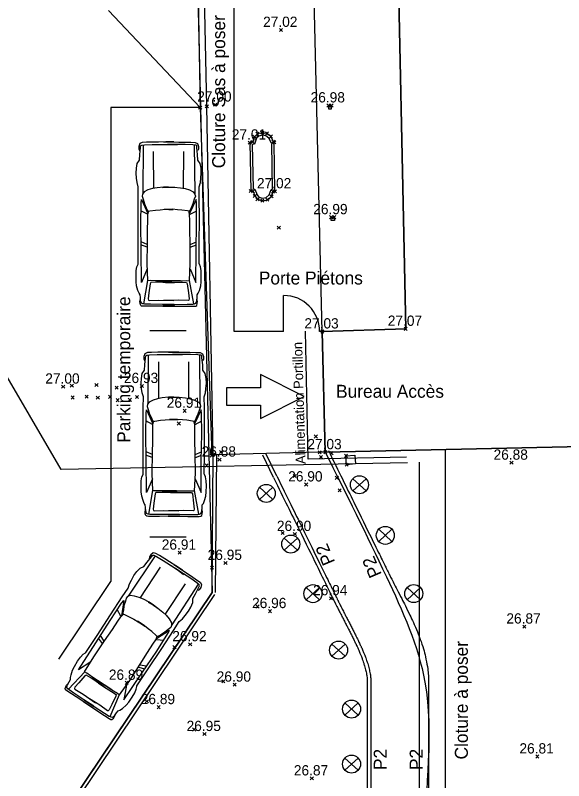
# Model space of a CAD drawing. Extents: x 37864 to 38032, y 453991 to 454052.
# Drawn here: x 37894.08 to 37909.31, y 454007.62 to 454028.87 of the extents above; entities that cross this region are included whole.
import ezdxf

# ---------------------------------------------------------------- set-up
doc = ezdxf.new("R2010")
doc.units = 0
for name, color, linetype in [('DH_CALCUL SURFACE-TEXTE', 7, 'Continuous'), ('GO MUR EXTERIEUR', 7, 'Continuous'), ('GO_MUR_INTERIEUR', 7, 'Continuous'), ('GO_POTEAU', 7, 'Continuous'), ('PS_Bolt', 7, 'Continuous'), ('PS_Dim', 7, 'Continuous'), ('PS_Hatch', 7, 'Continuous'), ('PS_Hidden', 7, 'Continuous'), ('PS_Mid', 7, 'Continuous'), ('PS_Object', 7, 'Continuous'), ('PS_Shape', 7, 'Continuous'), ('PS_Solid', 7, 'Continuous'), ('PS_Text', 7, 'Continuous'), ('PS_Weld', 7, 'Continuous'), ('SO_SANITAIRE DETAILLE', 7, 'Continuous')]:
    doc.layers.add(name, color=color, linetype=linetype)

# ---------------------------------------------------------------- blocks, each defined once
blk = doc.blocks.new('POTO_REC')
at = {"layer": 'PS_Weld'}
for p, q in [((0, 1), (1, 1)), ((0, 0), (0, 1)), ((1, 1), (1, 0)), ((1, 0), (0, 0))]:
    blk.add_line(p, q, dxfattribs=at)
blk = doc.blocks.new('POINT_DISPLAY')
for p, q in [((-0.04375, -0.04375), (0.04375, 0.04375)), ((-0.04375, 0.04375), (0.04375, -0.04375))]:
    blk.add_line(p, q)
blk = doc.blocks.new('POINTCOT')
blk.add_blockref('POINT_DISPLAY', (0, 0))
blk = doc.blocks.new('2AUTOT')
at = {"layer": 'PS_Object'}
for points in [[(-2.2368, -0.1259), (-2.2386, 0.2015), (-2.2354, 0.5377), (-2.2324, 0.697), (-2.2268, 0.7426), (-2.2084, 0.7838), (-2.144, 0.8083), (-2.0432, 0.8164), (-1.9712, 0.8202), (-1.9275, 0.8508), (-1.8518, 0.8827), (-1.7249, 0.9185), (-1.608, 0.9323), (-1.4401, 0.9339), (-1.298, 0.9313), (-1.1945, 0.9113), (-1.1215, 0.8812), (-1.1104, 0.8767), (-0.5447, 0.878), (0.1409, 0.8813), (0.7386, 0.8794), (1.0309, 0.8727), (1.1466, 0.9086), (1.2652, 0.9239), (1.4092, 0.9345), (1.5433, 0.9275), (1.677, 0.9028), (1.7685, 0.8402), (1.9202, 0.833), (2.1132, 0.8123), (2.1691, 0.8089), (2.1877, 0.7793), (2.1974, 0.6996), (2.2046, 0.4901), (2.2064, 0.2453), (2.2048, -0.0084), (2.1947, -0.2029)], [(2.2747, -0.1136), (2.2724, 0.1046), (2.27, 0.3126), (2.2713, 0.4704), (2.2666, 0.6444), (2.2593, 0.761), (2.2286, 0.8291), (2.1508, 0.8577), (2.0757, 0.8569), (2.0322, 0.8366)], [(-2.2848, -0.1314), (-2.2888, 0.4217), (-2.2909, 0.7314), (-2.2836, 0.7814), (-2.2655, 0.8064), (-2.2141, 0.8192), (-2.1613, 0.8262), (-2.1183, 0.817), (-2.0976, 0.8109)], [(-2.2271, 0.7235), (-1.5742, 0.6061)], [(-1.2494, 0.6227), (-1.6267, 0.7865), (-0.7381, 0.7926), (0.002, 0.8043), (0.5788, 0.7967), (0.6713, 0.7886), (0.2844, 0.6088)], [(-0.65, 0.6296), (-0.5861, 0.8002)], [(-0.5719, 0.6231), (-0.4967, 0.7965)], [(0.2639, 0.6208), (0.3616, 0.8058)], [(1.007, -0.1403), (1.0182, 0.0307), (1.0193, 0.1767), (1.0035, 0.3523), (0.9788, 0.4823), (0.9395, 0.605), (0.8856, 0.7131), (0.8242, 0.7593), (0.7669, 0.7701), (0.68, 0.7398), (0.5514, 0.701), (0.445, 0.6503), (0.3774, 0.6228), (0.3483, 0.6068), (0.3601, 0.5536), (0.3827, 0.3957), (0.3915, 0.2688), (0.4032, 0.1301), (0.4012, 0.0239), (0.4006, -0.0941)], [(2.1886, 0.7409), (0.8432, 0.7503)], [(-1.6299, -0.0629), (-1.6283, 0.1907), (-1.6233, 0.3735), (-1.6284, 0.5254), (-1.6632, 0.5449), (-1.9214, 0.5809), (-2.084, 0.5999), (-2.1242, 0.5899), (-2.1341, 0.5723), (-2.1215, 0.3067), (-2.1311, -0.1149)], [(-1.5848, -0.2978), (-1.5832, -0.0427), (-1.5806, 0.1815), (-1.5811, 0.4086), (-1.5755, 0.5339), (-1.5821, 0.6091), (-1.0895, 0.6288), (-0.5543, 0.6215), (-0.1709, 0.614), (0.1055, 0.6117), (0.2493, 0.6106), (0.3289, 0.5937), (0.3607, 0.5846)], [(0.9812, 0.4439), (2.0072, 0.4474)], [(-2.2368, 0.1834), (-2.2386, -0.144), (-2.2354, -0.4802), (-2.2324, -0.6394), (-2.2268, -0.6851), (-2.2084, -0.7263), (-2.144, -0.7508), (-2.0432, -0.7588), (-1.9712, -0.7627), (-1.9275, -0.7933), (-1.8518, -0.8251), (-1.7249, -0.861), (-1.608, -0.8748), (-1.4401, -0.8764), (-1.298, -0.8738), (-1.1945, -0.8538), (-1.1215, -0.8237), (-1.1104, -0.8192), (-0.5447, -0.8205), (0.1409, -0.8238), (0.7386, -0.8219), (1.0309, -0.8151), (1.1466, -0.8511), (1.2652, -0.8663), (1.4092, -0.877), (1.5433, -0.87), (1.677, -0.8453), (1.7685, -0.7827), (1.9202, -0.7755), (2.1132, -0.7548), (2.1691, -0.7514), (2.1877, -0.7218), (2.1974, -0.642), (2.2046, -0.4326), (2.2064, -0.1878), (2.2048, 0.0659), (2.1947, 0.2605)], [(-1.5848, 0.3553), (-1.5832, 0.1002), (-1.5806, -0.1239), (-1.5811, -0.351), (-1.5755, -0.4764), (-1.5821, -0.5516), (-1.0895, -0.5712), (-0.5543, -0.564), (-0.1709, -0.5565), (0.1055, -0.5542), (0.2493, -0.5531), (0.3289, -0.5362), (0.3607, -0.5271)], [(-2.2848, 0.1889), (-2.2888, -0.3641), (-2.2909, -0.6738), (-2.2836, -0.7239), (-2.2655, -0.7488), (-2.2141, -0.7617), (-2.1613, -0.7686), (-2.1183, -0.7595), (-2.0976, -0.7534)], [(-1.6299, 0.1205), (-1.6283, -0.1332), (-1.6233, -0.316), (-1.6284, -0.4679), (-1.6632, -0.4874), (-1.9214, -0.5234), (-2.084, -0.5424), (-2.1242, -0.5324), (-2.1341, -0.5148), (-2.1215, -0.2492), (-2.1311, 0.1725)], [(1.007, 0.1978), (1.0182, 0.0268), (1.0193, -0.1192), (1.0035, -0.2948), (0.9788, -0.4248), (0.9395, -0.5475), (0.8856, -0.6556), (0.8242, -0.7018), (0.7669, -0.7126), (0.68, -0.6823), (0.5514, -0.6435), (0.445, -0.5928), (0.3774, -0.5653), (0.3483, -0.5493), (0.3601, -0.4961), (0.3827, -0.3382), (0.3915, -0.2113), (0.4032, -0.0725), (0.4012, 0.0336), (0.4006, 0.1516)], [(2.2747, 0.1711), (2.2724, -0.0471), (2.27, -0.2551), (2.2713, -0.4129), (2.2666, -0.5869), (2.2593, -0.7035), (2.2286, -0.7716), (2.1508, -0.8002), (2.0757, -0.7993), (2.0322, -0.779)], [(0.9812, -0.3864), (2.0072, -0.3899)], [(-2.2271, -0.666), (-1.5742, -0.5486)], [(-1.2494, -0.5652), (-1.6267, -0.7289), (-0.7381, -0.735), (0.002, -0.7468), (0.5788, -0.7392), (0.6713, -0.731), (0.2844, -0.5513)], [(-0.65, -0.5721), (-0.5861, -0.7427)], [(-0.5719, -0.5656), (-0.4967, -0.739)], [(0.2639, -0.5633), (0.3616, -0.7483)], [(2.1886, -0.6834), (0.8432, -0.6928)]]:
    blk.add_lwpolyline(points, dxfattribs=at)
blk = doc.blocks.new('AUTD')
at = {"layer": 'PS_Object'}
blk.add_blockref('2AUTOT', (-2.1886, 0.6834), dxfattribs=at)
blk = doc.blocks.new('BORNANTI')
for p, q in [((-0.369, -0.338), (0.369, 0.338)), ((-0.369, 0.338), (0.369, -0.338))]:
    blk.add_line(p, q)
blk.add_circle((0, 0), 0.5)

msp = doc.modelspace()

# ---------------------------------------------------------------- linework, layer by layer
at = {"layer": 'GO MUR EXTERIEUR'}
msp.add_lwpolyline([(37904.652, 454032.841), (37904.92, 454020.167), (37902.603, 454020.093), (37902.686, 454016.74), (37922.017, 454017.171), (37921.708, 454033.195)], close=True, dxfattribs=at)
at = {"layer": 'GO_MUR_INTERIEUR'}
msp.add_lwpolyline([(37899.06, 454034.436), (37899.21, 454026.312), (37899.534, 454016.645)], dxfattribs=at)
at = {"layer": 'PS_Bolt'}
for points in [[(37901.27, 454025.348), (37901.249, 454025.367), (37901.177, 454025.51), (37901.065, 454025.594), (37900.941, 454025.614), (37900.801, 454025.583), (37900.719, 454025.503), (37900.664, 454025.358), (37900.588, 454025.34), (37900.618, 454023.996), (37900.679, 454023.987), (37900.729, 454023.857), (37900.803, 454023.766), (37900.94, 454023.726), (37901.078, 454023.753), (37901.192, 454023.847), (37901.233, 454023.975), (37901.286, 454023.986), (37901.27, 454025.348)], [(37901.2, 454025.317), (37901.192, 454025.324), (37901.122, 454025.464), (37901.037, 454025.528), (37900.943, 454025.543), (37900.836, 454025.519), (37900.779, 454025.463), (37900.716, 454025.298), (37900.659, 454025.285), (37900.687, 454024.057), (37900.73, 454024.05), (37900.79, 454023.892), (37900.843, 454023.827), (37900.943, 454023.798), (37901.048, 454023.818), (37901.132, 454023.888), (37901.179, 454024.036), (37901.216, 454024.043), (37901.2, 454025.317)]]:
    msp.add_lwpolyline(points, dxfattribs=at)
at = {"layer": 'PS_Dim'}
for p, q in [((37900.154, 454020.093), (37900.154, 454030.534)), ((37901.53, 454020.093), (37901.53, 454021.093)), ((37901.53, 454020.093), (37900.154, 454020.093)), ((37902.676, 454020.093), (37902.53, 454020.093)), ((37906.023, 454001.592), (37906.023, 454016.814))]:
    msp.add_line(p, q, dxfattribs=at)
msp.add_arc((37901.53, 454020.093), 1, 360, 90, dxfattribs=at)
at = {"layer": 'PS_Hatch'}
msp.add_lwpolyline([(37902.603, 454020.093), (37902.29, 454032.792), (37904.652, 454032.841), (37904.92, 454020.167), (37902.603, 454020.093)], dxfattribs=at)
at = {"layer": 'PS_Hidden'}
for p, q in [((37896.73, 454026.312), (37896.73, 454013.149)), ((37899.21, 454026.312), (37896.73, 454026.312)), ((37898.82, 454020.114), (37897.814, 454020.114)), ((37901.34, 454016.079), (37901.039, 454016.705)), ((37901.249, 454016.035), (37900.949, 454016.662)), ((37898.82, 454014.385), (37897.814, 454014.385))]:
    msp.add_line(p, q, dxfattribs=at)
msp.add_lwpolyline([(37902.1, 454018.289), (37900.885, 454018.896), (37900.885, 454018.531), (37899.943, 454018.531), (37899.943, 454018.047), (37900.885, 454018.047), (37900.885, 454017.681)], close=True, dxfattribs=at)
msp.add_spline([(37902.686, 454016.74), (37904.384, 454013.284), (37905.453, 454010.356), (37905.453, 454005.953), (37905.453, 454003.832), (37904.955, 454001.594)], degree=3, dxfattribs=at)
for points in [[(37902.776, 454016.784), (37903.066, 454016.194), (37903.501, 454015.308), (37904.008, 454014.275), (37904.262, 454013.759), (37904.389, 454013.501), (37904.446, 454013.385), (37904.466, 454013.344), (37904.471, 454013.335), (37904.473, 454013.33), (37904.48, 454013.316), (37904.493, 454013.289), (37904.507, 454013.261), (37904.589, 454013.096), (37904.666, 454012.948), (37904.821, 454012.649), (37904.899, 454012.498), (37905.049, 454012.194), (37905.122, 454012.04), (37905.256, 454011.728), (37905.318, 454011.57), (37905.423, 454011.25), (37905.466, 454011.087), (37905.529, 454010.758), (37905.549, 454010.59), (37905.553, 454010.399), (37905.553, 454010.378), (37905.553, 454010.356), (37905.553, 454010.356), (37905.553, 454010.355), (37905.553, 454010.354), (37905.553, 454010.352), (37905.553, 454010.347), (37905.553, 454010.338), (37905.553, 454010.32), (37905.553, 454010.264), (37905.553, 454010.13), (37905.553, 454009.843), (37905.553, 454008.938), (37905.553, 454007.787), (37905.553, 454006.636), (37905.553, 454006.138), (37905.553, 454005.966), (37905.553, 454005.958), (37905.553, 454005.953), (37905.553, 454005.95), (37905.553, 454005.938), (37905.553, 454005.907), (37905.554, 454005.876), (37905.554, 454005.815), (37905.555, 454005.774), (37905.557, 454005.652), (37905.559, 454005.57), (37905.567, 454005.323), (37905.574, 454005.158), (37905.584, 454004.827), (37905.588, 454004.661), (37905.587, 454004.328), (37905.582, 454004.162), (37905.566, 454003.955), (37905.562, 454003.913), (37905.556, 454003.851), (37905.554, 454003.83), (37905.549, 454003.789), (37905.547, 454003.768), (37905.534, 454003.665), (37905.522, 454003.583), (37905.481, 454003.337), (37905.448, 454003.174), (37905.374, 454002.85), (37905.334, 454002.689), (37905.251, 454002.369), (37905.209, 454002.209), (37905.128, 454001.89), (37905.088, 454001.731), (37905.053, 454001.572)], [(37901.34, 454016.079), (37901.63, 454015.488), (37902.065, 454014.603), (37902.572, 454013.57), (37902.826, 454013.053), (37902.953, 454012.795), (37903.01, 454012.68), (37903.031, 454012.636), (37903.035, 454012.628), (37903.037, 454012.624), (37903.038, 454012.623), (37903.038, 454012.622), (37903.038, 454012.622), (37903.039, 454012.621), (37903.044, 454012.61), (37903.049, 454012.599), (37903.065, 454012.568), (37903.075, 454012.548), (37903.125, 454012.447), (37903.166, 454012.368), (37903.245, 454012.213), (37903.285, 454012.137), (37903.361, 454011.989), (37903.399, 454011.916), (37903.471, 454011.774), (37903.506, 454011.705), (37903.573, 454011.57), (37903.605, 454011.504), (37903.665, 454011.375), (37903.693, 454011.313), (37903.745, 454011.191), (37903.769, 454011.132), (37903.813, 454011.019), (37903.832, 454010.964), (37903.867, 454010.859), (37903.882, 454010.808), (37903.907, 454010.712), (37903.918, 454010.666), (37903.935, 454010.578), (37903.941, 454010.537), (37903.95, 454010.457), (37903.952, 454010.42), (37903.953, 454010.374), (37903.953, 454010.365), (37903.953, 454010.356), (37903.953, 454010.356), (37903.953, 454010.356), (37903.953, 454010.356), (37903.953, 454010.355), (37903.953, 454010.354), (37903.953, 454010.352), (37903.953, 454010.347), (37903.953, 454010.338), (37903.953, 454010.32), (37903.953, 454010.264), (37903.953, 454010.13), (37903.953, 454009.843), (37903.953, 454008.938), (37903.953, 454007.787), (37903.953, 454006.636), (37903.953, 454006.138), (37903.953, 454005.966), (37903.953, 454005.957), (37903.953, 454005.954), (37903.953, 454005.953), (37903.953, 454005.953), (37903.953, 454005.953), (37903.953, 454005.952), (37903.953, 454005.95), (37903.953, 454005.936), (37903.953, 454005.923), (37903.953, 454005.888), (37903.954, 454005.864), (37903.954, 454005.795), (37903.955, 454005.749), (37903.958, 454005.612), (37903.96, 454005.523), (37903.966, 454005.35), (37903.969, 454005.265), (37903.975, 454005.1), (37903.977, 454005.02), (37903.982, 454004.864), (37903.984, 454004.788), (37903.987, 454004.641), (37903.988, 454004.57), (37903.987, 454004.433), (37903.986, 454004.366), (37903.981, 454004.238), (37903.978, 454004.176), (37903.971, 454004.088), (37903.969, 454004.059), (37903.965, 454004.023), (37903.964, 454004.016), (37903.963, 454004.005), (37903.963, 454004.001), (37903.962, 454003.997), (37903.962, 454003.995), (37903.962, 454003.995), (37903.962, 454003.994), (37903.962, 454003.992), (37903.96, 454003.975), (37903.958, 454003.959), (37903.949, 454003.885), (37903.94, 454003.825), (37903.919, 454003.7), (37903.908, 454003.636), (37903.881, 454003.504), (37903.867, 454003.436), (37903.835, 454003.297), (37903.818, 454003.226), (37903.782, 454003.079), (37903.763, 454003.005), (37903.723, 454002.851), (37903.703, 454002.773), (37903.661, 454002.612), (37903.64, 454002.53), (37903.597, 454002.362), (37903.575, 454002.276), (37903.533, 454002.101), (37903.512, 454002.011), (37903.491, 454001.92)], [(37901.25, 454016.035), (37901.54, 454015.444), (37901.975, 454014.559), (37902.483, 454013.526), (37902.736, 454013.009), (37902.863, 454012.751), (37902.918, 454012.64), (37902.938, 454012.599), (37902.941, 454012.592), (37902.945, 454012.585), (37902.946, 454012.582), (37902.947, 454012.58), (37902.948, 454012.579), (37902.948, 454012.579), (37902.948, 454012.578), (37902.948, 454012.578), (37902.949, 454012.577), (37902.949, 454012.576), (37902.955, 454012.565), (37902.96, 454012.555), (37902.975, 454012.524), (37902.985, 454012.503), (37903.036, 454012.402), (37903.077, 454012.322), (37903.156, 454012.167), (37903.196, 454012.091), (37903.272, 454011.943), (37903.31, 454011.87), (37903.382, 454011.729), (37903.417, 454011.66), (37903.483, 454011.526), (37903.515, 454011.461), (37903.574, 454011.334), (37903.602, 454011.272), (37903.653, 454011.153), (37903.676, 454011.095), (37903.719, 454010.984), (37903.738, 454010.931), (37903.771, 454010.829), (37903.786, 454010.781), (37903.81, 454010.688), (37903.82, 454010.645), (37903.836, 454010.562), (37903.842, 454010.523), (37903.85, 454010.449), (37903.852, 454010.414), (37903.853, 454010.377), (37903.853, 454010.373), (37903.853, 454010.367), (37903.853, 454010.364), (37903.853, 454010.36), (37903.853, 454010.358), (37903.853, 454010.357), (37903.853, 454010.357), (37903.853, 454010.357), (37903.853, 454010.356), (37903.853, 454010.356), (37903.853, 454010.356), (37903.853, 454010.356), (37903.853, 454010.356), (37903.853, 454010.355), (37903.853, 454010.355), (37903.853, 454010.354), (37903.853, 454010.352), (37903.853, 454010.347), (37903.853, 454010.338), (37903.853, 454010.32), (37903.853, 454010.264), (37903.853, 454010.13), (37903.853, 454009.843), (37903.853, 454008.938), (37903.853, 454007.787), (37903.853, 454006.636), (37903.853, 454006.143), (37903.853, 454005.973), (37903.853, 454005.966), (37903.853, 454005.958), (37903.853, 454005.955), (37903.853, 454005.954), (37903.853, 454005.953), (37903.853, 454005.953), (37903.853, 454005.952), (37903.853, 454005.95), (37903.853, 454005.948), (37903.853, 454005.935), (37903.853, 454005.923), (37903.853, 454005.887), (37903.854, 454005.864), (37903.854, 454005.793), (37903.855, 454005.747), (37903.858, 454005.61), (37903.86, 454005.52), (37903.866, 454005.346), (37903.869, 454005.261), (37903.875, 454005.097), (37903.878, 454005.017), (37903.882, 454004.861), (37903.884, 454004.786), (37903.887, 454004.64), (37903.888, 454004.57), (37903.887, 454004.434), (37903.886, 454004.368), (37903.881, 454004.243), (37903.878, 454004.182), (37903.872, 454004.096), (37903.869, 454004.068), (37903.866, 454004.033), (37903.865, 454004.026), (37903.864, 454004.016), (37903.864, 454004.013), (37903.863, 454004.008), (37903.863, 454004.008), (37903.863, 454004.006), (37903.863, 454004.006), (37903.863, 454004.005), (37903.862, 454004.003), (37903.862, 454004.001), (37903.86, 454003.985), (37903.859, 454003.971), (37903.85, 454003.899), (37903.841, 454003.84), (37903.821, 454003.718), (37903.809, 454003.654), (37903.783, 454003.525), (37903.769, 454003.458), (37903.738, 454003.32), (37903.721, 454003.249), (37903.685, 454003.104), (37903.666, 454003.029), (37903.627, 454002.876), (37903.606, 454002.798), (37903.564, 454002.637), (37903.543, 454002.555), (37903.5, 454002.387), (37903.478, 454002.3), (37903.435, 454002.124), (37903.414, 454002.034), (37903.394, 454001.941)]]:
    msp.add_open_spline(points, degree=3, dxfattribs=at)
at = {"layer": 'PS_Mid'}
msp.add_lwpolyline([(37902.686, 454016.74), (37902.53, 454016.739), (37899.575, 454016.672), (37899.397, 454026.348), (37899.231, 454034.242), (37905.827, 454034.425), (37913.049, 454034.558), (37921.676, 454034.732), (37921.802, 454033.217), (37921.708, 454033.195)], dxfattribs=at)
at = {"layer": 'PS_Object'}
for p, q in [((37895.353, 454016.257), (37888.689, 454027.599)), ((37905.292, 454016.464), (37905.292, 454001.738)), ((37904.969, 454016.447), (37895.353, 454016.257))]:
    msp.add_line(p, q, dxfattribs=at)
for points in [[(37889.343, 454030.528), (37899.117, 454030.549), (37899.54, 454012.849), (37895.242, 454006.442), (37895.242, 454005.264), (37889.943, 454005.178)], [(37904.94, 454016.607), (37902.211, 454016.551), (37902.139, 454020.1)]]:
    msp.add_lwpolyline(points, dxfattribs=at)
at = {"layer": 'PS_Shape'}
msp.add_line((37895.285, 454010.994), (37896.73, 454013.149), dxfattribs=at)
at = {"layer": 'PS_Solid'}
msp.add_lwpolyline([(37921.708, 454033.195), (37922.017, 454017.171), (37902.686, 454016.74), (37902.603, 454020.093), (37904.92, 454020.167), (37904.652, 454032.841), (37921.708, 454033.195)], dxfattribs=at)
at = {"layer": 'PS_Text'}
for points in [[(37902.774, 454026.281), (37902.859, 454026.279), (37902.861, 454026.369), (37902.776, 454026.371)], [(37902.85, 454023.268), (37902.936, 454023.27), (37902.938, 454023.18), (37902.852, 454023.178)]]:
    msp.add_lwpolyline(points, close=True, dxfattribs=at)
at = {"layer": 'SO_SANITAIRE DETAILLE'}
for p, q in [((37896.668, 454029.009), (37899.21, 454026.312)), ((37899.54, 454012.849), (37899.575, 454016.672)), ((37899.64, 454012.848), (37899.675, 454016.671)), ((37895.242, 454006.442), (37899.54, 454012.849)), ((37895.325, 454006.386), (37899.623, 454012.793))]:
    msp.add_line(p, q, dxfattribs=at)

# ---------------------------------------------------------------- block references
at = {"layer": 'DH_CALCUL SURFACE-TEXTE', "rotation": 2.2526485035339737e-05}
for p in [(37901.457, 454028.469), (37899.21, 454026.312), (37899.397, 454026.348), (37899.628, 454026.395), (37902.776, 454026.371), (37902.861, 454026.369), (37900.801, 454025.583), (37900.941, 454025.614), (37901.065, 454025.594), (37900.664, 454025.358), (37900.719, 454025.503), (37901.177, 454025.51), (37901.249, 454025.367), (37900.588, 454025.34), (37901.27, 454025.348), (37900.618, 454023.996), (37900.679, 454023.987), (37901.233, 454023.975), (37901.286, 454023.986), (37900.729, 454023.857), (37900.803, 454023.766), (37900.94, 454023.726), (37901.078, 454023.753), (37901.192, 454023.847), (37902.85, 454023.268), (37902.936, 454023.27), (37901.397, 454022.975), (37902.603, 454020.093), (37904.92, 454020.167), (37904.92, 454020.167), (37895.407, 454018.562), (37895.647, 454018.588), (37896.33, 454018.605), (37897.59, 454018.578), (37896.893, 454018.535), (37895.67, 454018.26), (37896.059, 454018.283), (37896.369, 454018.256), (37896.707, 454018.28), (37896.92, 454018.188), (37897.259, 454018.196), (37897.457, 454018.275), (37898.781, 454017.891), (37898.617, 454017.537), (37902.422, 454017.176), (37899.534, 454016.645), (37899.575, 454016.672), (37899.79, 454016.749), (37902.53, 454016.739), (37902.686, 454016.74), (37902.864, 454016.715), (37903.261, 454016.638), (37899.75, 454016.536), (37902.566, 454016.609), (37907.858, 454016.448), (37899.392, 454016.373), (37903.28, 454016.394), (37901.836, 454016.078), (37903.007, 454016.027), (37902.154, 454015.845), (37903.088, 454015.684), (37901.502, 454014.496), (37901.84, 454014.469), (37898.642, 454013.949), (37899.916, 454013.665), (37899.538, 454013.535), (37902.846, 454012.684), (37900.804, 454012.454), (37901.15, 454012.328), (37908.214, 454011.898), (37898.498, 454011.325), (37898.934, 454011.406), (37897.172, 454010.335), (37899.853, 454010.379), (37900.168, 454010.284), (37897.728, 454009.824), (37898.059, 454009.66), (37899.044, 454009.041), (37899.331, 454008.913), (37908.577, 454008.289), (37902.311, 454007.681)]:
    msp.add_blockref('POINTCOT', p, dxfattribs=at)
at = {"layer": 'PS_Bolt'}
for name, p, xscale, yscale, rotation in [('POTO_REC', (37903.28, 454016.394), 0.24999999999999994, 0.24999999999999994, 4.495003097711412), ('BORNANTI', (37903.635, 454015.836), 0.5000000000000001, 0.5, 2.2526485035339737e-05), ('BORNANTI', (37901.048, 454015.597), 0.5000000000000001, 0.5, 2.2526485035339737e-05), ('BORNANTI', (37904.354, 454014.432), 0.5000000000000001, 0.5, 2.2526485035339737e-05), ('BORNANTI', (37901.726, 454014.189), 0.5000000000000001, 0.5, 2.2526485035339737e-05), ('BORNANTI', (37905.145, 454012.814), 0.5000000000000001, 0.5, 2.2526485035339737e-05), ('BORNANTI', (37902.342, 454012.812), 0.5000000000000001, 0.5, 2.2526485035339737e-05), ('BORNANTI', (37903.056, 454011.244), 0.5000000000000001, 0.5, 2.2526485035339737e-05), ('BORNANTI', (37903.415, 454009.607), 0.5000000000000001, 0.5, 2.2526485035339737e-05), ('BORNANTI', (37903.415, 454008.078), 0.5000000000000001, 0.5, 2.2526485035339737e-05)]:
    msp.add_blockref(name, p, dxfattribs=dict(at, xscale=xscale, yscale=yscale, rotation=rotation))
at = {"layer": 'PS_Hidden'}
for p, rotation in [((37899.049, 454025.273), 89.99999999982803), ((37899.19, 454019.436), 89.99999999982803), ((37899.151, 454013.08), 56.70960119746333)]:
    msp.add_blockref('AUTD', p, dxfattribs=dict(at, rotation=rotation))

# ---------------------------------------------------------------- texts
at = {"layer": 'GO_POTEAU'}
for s, p in [('27.02', (37900.959, 454028.553)), ('27.00', (37899.13, 454026.479)), ('26.98', (37902.278, 454026.455)), ('27.01', (37900.09, 454025.424)), ('27.02', (37900.788, 454024.07)), ('26.99', (37902.352, 454023.351)), ('27.07', (37904.422, 454020.251)), ('27.03', (37902.105, 454020.177)), ('27.00', (37894.909, 454018.646)), ('26.93', (37897.092, 454018.662)), ('26.91', (37898.283, 454017.975)), ('27.03', (37902.188, 454016.824)), ('26.88', (37899.252, 454016.62)), ('26.88', (37907.36, 454016.532)), ('26.90', (37901.656, 454015.928)), ('26.90', (37901.342, 454014.553)), ('26.91', (37898.144, 454014.033)), ('26.95', (37899.419, 454013.749)), ('26.94', (37902.348, 454012.768)), ('26.96', (37900.652, 454012.411)), ('26.87', (37907.716, 454011.982)), ('26.92', (37898.436, 454011.49)), ('26.89', (37896.674, 454010.419)), ('26.90', (37899.67, 454010.368)), ('26.89', (37897.561, 454009.744)), ('26.95', (37898.833, 454008.997)), ('26.81', (37908.079, 454008.373)), ('26.87', (37901.813, 454007.764))]:
    msp.add_text(s, height=0.285, rotation=0, dxfattribs=at).set_placement(p)
at = {"layer": 'PS_Hidden'}
for s, rotation, p in [('Cloture Sas à poser', 90, (37899.905, 454024.625)), ('Porte Piétons', 360, (37900.84, 454021.399)), ('Parking temporaire', 90, (37897.269, 454017.001)), ('Bureau Accès', 360, (37902.986, 454018.253)), ('P2', 113.1085, (37902.965, 454013.693)), ('P2', 113.1085, (37904.262, 454013.349)), ('Cloture à poser', 90, (37906.646, 454008.207)), ('P2', 90, (37904.392, 454007.913)), ('P2', 90, (37905.39, 454007.913))]:
    msp.add_text(s, height=0.36, rotation=rotation, dxfattribs=at).set_placement(p)
at = {"layer": 'PS_Object'}
msp.add_text('Alimentation Portillon', height=0.27, rotation=91.6221, dxfattribs=at).set_placement((37902.14, 454016.416))

doc.saveas('drawing.dxf')
